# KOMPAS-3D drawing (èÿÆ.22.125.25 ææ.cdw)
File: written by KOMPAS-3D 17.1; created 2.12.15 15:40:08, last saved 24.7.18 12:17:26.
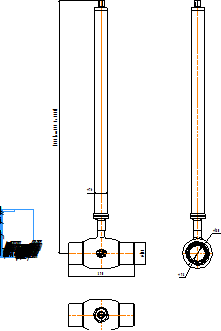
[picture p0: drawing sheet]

Sheet 1: A4, portrait

Title block, sheet 1: name: КШТ.22.125.25 С/С; sheets: 1; organisation: ООО "АДЛ Групп"; sheet format: A4; stored path: C:\Users\kka\KOMPAS_Work\Модели кранов для исследований\DN50\С удлинением\КШГ.32.050.40 СС ГЧ _ Шаровой кран БИВАЛ Ду50 Ру4 МПа редуцированный под приварку, с удлинением штока H=1100.cdw

Views: Вид 1, Спереди
Referenced files in C:\Users\kka\KOMPAS_Work\Модели кранов для исследований\DN125\С удлинением\: КШТ.22.125.25 СС.a3d, КШТ.22.125.25 СС.a3d!УШ.281.00.00!Деталь (локальная).m3d
Referenced files in C:\Users\kka\KOMPAS_Work\Модели кранов для исследований\DN125\: АПТА.0203-2623.12.01 _ Корпус крана Ду125.m3d, АПТА.0203-2623.13.01 _ Корпус штока Ду125.m3d, АПТА.0203-2623.12.02 _ Шайба фрикционная Ду125.m3d, АПТА.0203-2623.11.02 _ Крышка штока Ду125.m3d, Кольцо Viton 24.2x3.m3d, Кольцо EPDM 24.2x3.m3d, АПТА.0203-2623.13.02 _ Фланец приварной Ду125.m3d, Шар125.m3d, АПТА.0203-2623.14.02 _ Пластина штока Ду125.m3d, АПТА.0203-2623.14.01 _ Шток Ду125.m3d, Шпонка 8x7x28 ГОСТ 23360-78.m3d, АПТА.0203-1937.00.00 _ Кран шаровой сварной Ду125 (Труба по ГОСТ).a3d!АПТА.0203-1937.00.00!Деталь (локальная).m3d, АПТА.0203-1937.00.00 _ Кран шаровой сварной Ду125 (Труба по ГОСТ).a3d!АПТА.0203-1937.00.00!Деталь (локальная) 1.m3d, Втулка ГОСТ ИСО 3547-1-2006 25 B 28х25-Р1-С.m3d, АПТА.0203-2623.02.03 _ Пружина тарельчатая Ду125.m3d, АПТА.0203-1937.03.01 _ Патрубок сварной точенный Ду125 (труба по ГОСТ).m3d, АПТА.0203-2623.02.05 _ Уплотнение седловое Ду125.m3d, АПТА.0203-2623.02.04 _ Кольцо опорное Ду125.m3d, АПТА.0203-2623.02.02 _ Кольцо горловое Ду125.m3d, АПТА.0203-1937.00.00 _ Кран шаровой сварной Ду125 (Труба по ГОСТ).a3d!АПТА.0203-1937.00.00!Деталь (локальная) 2.m3d, АПТА.0203-2623.03.01 _ Втулка Ду125.m3d, АПТА.0203-2621.03.01 _ Рукоятка Ду100-125.m3d, АПТА.0203-2623.03.02 _ Пластина стопорная Ду125.m3d, АПТА.0203-2623.03.00 _ Ручка Ду125.a3d, АПТА.0203-1937.00.00 _ Кран шаровой сварной Ду125 (Труба по ГОСТ).a3d!АПТА.0203-1937.00.00!Деталь (локальная) 1 1.m3d, АПТА.0203-1937.00.00 _ Кран шаровой сварной Ду125 (Труба по ГОСТ).a3d
Referenced files in C:\Program Files\ASCON\KOMPAS-3D v17\Libs\PartLib\DATA\VAULT\methods\kompas\3d\: PLib_Check_spring_rings_GOST_13942_911.m3d, PLib_Pin_ISO_8745_1100.m3d, PLib_Screw_GOST_8878-84_900.m3d, PLib_Pin_3128_712.m3d, PLib_Bolt_1_900.m3d, PLib_Washer_2_712.m3d
Referenced files in C:\Users\kka\KOMPAS_Work\Краны шаровые сварные регулирующие БИВАЛ ф. ADL\Труба DIN\DN125\: АПТА.0203-2621.11.02 _ Подкладка для кольца Ду100-125.m3d
Referenced files in C:\Users\kka\KOMPAS_Work\Модели кранов для исследований\DN65\: АПТА.0203-2617.03.03 _ Ухватка Ду65-200.m3d
Referenced files in C:\Users\kka\KOMPAS_Work\!Trash\Редукторы\Редуктор серии Q\компас 3d\: Q-400-S.m3d
Referenced files in C:\Users\kka\KOMPAS_Work\!Trash\Штурвалы\: штурвал диаметр 160.m3d
Referenced files in C:\Users\kka\KOMPAS_Work\Удлинения БИВАЛ ф. ADL\Небюджет\Удлинения_2010\УШДн125\: УШ.281.00.01 _ Фланец нижний Ду125.m3d, УШ.276.01.01 _ Втулка верхняя Ду100-125.m3d, УШ.281.01.02 _ Втулка нижняя Ду125.m3d, УШ.276.00.03 _ Прокладка Ду100-125.m3d, УШ.261.00.06 _ Кольцо запорное Ду20-150.m3d, УШ.281.00.00 _ Удлинение штока Ду125.a3d!УШ.281.00.00!Деталь (локальная).m3d, УШ.281.00.00 _ Удлинение штока Ду125.a3d!УШ.281.00.00!Деталь (локальная) 1.m3d, УШ.281.00.00 _ Удлинение штока Ду125.a3d
Referenced files in C:\Users\kka\KOMPAS_Work\Удлинения БИВАЛ ф. ADL\Небюджет\Удлинения_2010\УШДн100\: Шток_100.m3d, УШ.276.00.06 _ Крышка корпуса Ду100-150.m3d, Шпонка 8х7х40 ГОСТ 23360-80.m3d
Referenced files in C:\Users\kka\KOMPAS_Work\!Trash\АГТО 099.00.00 Кран для выставки Ду150 ПП П-Э патрубки\Удлинение 200\: Кольцо 036-041-30-1-2 ГОСТ 9833-73ГОСТ 18829-73.m3d
Referenced files in C:\Users\kka\KOMPAS_Work\Модели кранов для исследований\DN80\С удлинением\: КШТ.22.080.25 СС.a3d, КШГ.35.065.25 СС.a3d!КШГ.45.065.10 СС!Деталь (локальная).m3d
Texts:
  Klimkovich
  ADL
  (от 377 до 5000)
  УШ.281.00.00
  Рама для чертежей
  Лит-Масса-Масштаб
  Материал-Предприятие
  Масштаб
  Изм.
  Лист
  № докум.
  Подп.
  Дата
  Лит.
  Разраб.
  Пров.
  Т.контр.
  Листов
  Внимание! Данный продукт является объектом авторского права ООО «Торговый Дом АДЛ».
  Запрещается изменение, копирование, распространение
  (в том числе путем копирования на другие сайты и ресурсы в Интернете)
  или любое иное использование информации и объектов без предварительного
  согласия правообладателя (ООО «Торговый Дом АДЛ»).
  Н.контр.
  Утв.
  ООО "Торговый дом АДЛ"
  Изменение
  Номер документа
  Подпись
  Обозначение документа
  Наименование изделия
  Масса изделия по ГОСТ 2.109-73
  Порядковый номер листа
  Общее количество листов в документе
  Характер работы, выполненной лицом, подписавшим документ
  Наименование или индекс предприятия, выпускающего документ
  Инв. № подл.
  Подп. и дата
  Взам. инв. №
  Инв. № дубл.
  Инвентарный номер подлинника по ГОСТ 2.501-68
  Подпись принявшего подлинник в отдел технической документации
  Инвентарный номер подлинника, взамен которого выпущен данный подлинник
  Инвентарный номер дубликата по ГОСТ 2.502-68
  Подпись принявшего дубликат в отдел технической документации
  Справ. №
  Перв. примен.
  Обозначение документа, взамен или на основании которого выпущен данный документ
  Обозначение документа, в котором впервые записан данный документ
  Подпись лица, копировавшего чертеж
  Обозначение формата листа
  !Рама для чертежа
  Корпус крана Ду125
  АПТА.0203-2623.12.01
  Корпус штока Ду125
  АПТА.0203-2623.13.01
  Шайба фрикционная Ду125
  АПТА.0203-2623.12.02
  Крышка штока Ду125
  АПТА.0203-2623.11.02
  Кольцо Viton 24.2x3
  Кольцо EPDM 24.2x3
  Фланец приварной Ду100 ПП
  КШП.ГИ.100.13.02-01
  Шар Ду125
  АПТА.0203-2623.11.01
  Пластина штока Ду125
  АПТА.0203-2623.14.02
  Шток Ду125
  АПТА.0203-2623.14.01
  Шпонка 8x7x28 ГОСТ 23360-78
  Деталь (локальная)
  Кольцо A25.50 ХГА ГОСТ 13942-86
  Втулка ГОСТ ИСО 3547-1-2006  25 B 28х25-Р1-С
  Подкладка для кольца Ду100-125
  АПТА.0203-2621.11.02
  Пружина тарельчатая Ду125
  АПТА.0203-2623.02.03
  Патрубок сварной точенный Ду125 (труба по ГОСТ)
  АПТА.0203-1937.03.01
  Уплотнение седловое Ду125
  АПТА.0203-2623.02.05
  Кольцо опорное Ду125
  АПТА.0203-2623.02.04
  Кольцо горловое Ду125
  АПТА.0203-2623.02.02
  Grooved pin ISO 8745 - 10 x 24 - A1
  Втулка Ду125
  АПТА.0203-2623.03.01
  Рукоятка Ду100-125
  АПТА.0203-2621.03.01
  Ухватка Ду65-200
  АПТА.0203-2617.03.03
  Пластина стопорная Ду125
  АПТА.0203-2623.03.02
  Ручка Ду125
  АПТА.0203-2623.03.00
  штурвал диаметр 160
  Винт М6-6gx10.14H.019 ГОСТ 8878-93
  Кран шаровой сварной Ду125 (Труба по ГОСТ)
  АПТА.0203-1937.00.00
  Фланец нижний Ду125
  УШ.281.00.01
  Втулка верхняя Ду100-125
  УШ.276.01.01
  Втулка нижняя Ду125
  УШ.281.01.02
  Прокладка Ду100-125
  УШ.276.00.03
  Кольцо запорное Ду20-150
  УШ.261.00.06
  Головка штока Ду100-150
  УШ.276.00.02
  Крышка корпуса Ду100-150
  УШ.276.00.06
  Удлинитель
  Кольцо A36.65 ГОСТ 13942-86
  Штифт 10x20 ГОСТ 3128-70
  Болт М8-6gx28.68.019 ГОСТ 7796-70
  Шайба 8 65Г 019 ГОСТ 6402-70
  Шпонка 8х7х40 ГОСТ 23360-80
  Кольцо 036-041-30-1-2 ГОСТ 9833-73/ГОСТ 18829-73
  Удлинение штока Ду125
  Патрубок
Dimensions and other numbers on the sheet: 1500; 76; 390; 133; 1:1; 1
